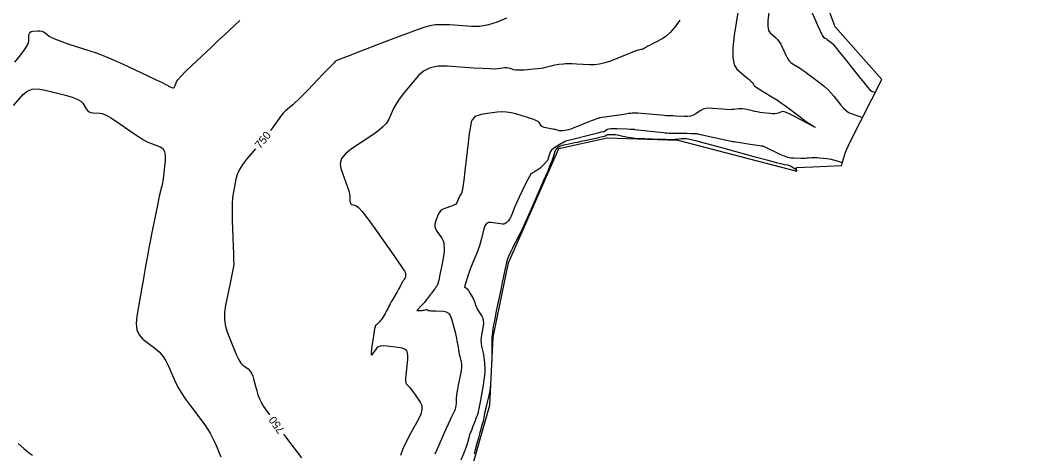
# Model space of a CAD drawing. Extents: x 2079879 to 2092887, y 778083 to 784051.
# Drawn here: x 2084488.3 to 2084844.9, y 780660.6 to 780812.3 of the extents above; entities that cross this region are included whole.
import ezdxf

# ---------------------------------------------------------------- set-up
doc = ezdxf.new("R2010")
doc.units = 0
for name, color, linetype in [('DT_X_Contour_Major', 7, 'Continuous'), ('DT_X_Contour_Minor', 7, 'Continuous'), ('DT_X_TIN_Hull', 7, 'Continuous')]:
    doc.layers.add(name, color=color, linetype=linetype)

msp = doc.modelspace()

# ---------------------------------------------------------------- linework, layer by layer
at = {"layer": 'DT_X_Contour_Major'}
for points in [[(2084658.31, 780813.13), (2084655.13, 780811.71), (2084652.04, 780810.75), (2084649.04, 780810.25), (2084646.14, 780810.21), (2084638.53, 780810.73), (2084635.85, 780810.83), (2084633.5, 780810.74), (2084631.49, 780810.47), (2084629.82, 780810.01), (2084625.82, 780808.53), (2084624.06, 780807.88), (2084621.76, 780807.01), (2084618.92, 780805.94), (2084615.56, 780804.65), (2084605.87, 780800.96), (2084602.68, 780799.73), (2084600.39, 780798.84), (2084598.99, 780798.27), (2084598.48, 780798.04), (2084598.32, 780797.84), (2084598.02, 780797.52), (2084597.24, 780796.7), (2084595.97, 780795.38), (2084594.23, 780793.56), (2084588.94, 780788.05), (2084587.11, 780786.17), (2084585.61, 780784.67), (2084584.43, 780783.54), (2084583.56, 780782.79), (2084581.7, 780781.29), (2084580.99, 780780.66), (2084580.26, 780779.9), (2084579.52, 780779.01), (2084578.76, 780777.99), (2084576.71, 780775.1), (2084575.84, 780773.91), (2084575.81, 780773.87)], [(2084486.28, 780797.73), (2084488.42, 780800.3), (2084489.95, 780802.35), (2084490.88, 780803.88), (2084491.2, 780804.9), (2084491.24, 780806.92), (2084491.34, 780807.58), (2084491.6, 780808.08), (2084492.04, 780808.39), (2084492.64, 780808.53), (2084494.47, 780808.66), (2084495.13, 780808.65), (2084495.76, 780808.53), (2084496.35, 780808.28), (2084496.91, 780807.92), (2084498.33, 780806.8), (2084499.14, 780806.32), (2084500.51, 780805.72), (2084502.44, 780805.01), (2084504.92, 780804.18), (2084512.27, 780801.82), (2084515.08, 780800.85), (2084518.02, 780799.72), (2084521.08, 780798.44), (2084524.26, 780796.99), (2084532.9, 780792.9), (2084535.76, 780791.55), (2084537.84, 780790.55), (2084539.16, 780789.91), (2084539.7, 780789.62), (2084540.12, 780789.34), (2084540.29, 780789.23), (2084540.48, 780789.13), (2084540.7, 780789.03), (2084540.93, 780788.94), (2084541.59, 780788.69), (2084541.83, 780788.67), (2084542.04, 780788.8), (2084542.24, 780789.07), (2084542.42, 780789.48), (2084542.86, 780790.77), (2084543.33, 780791.5), (2084544.39, 780792.71), (2084546.04, 780794.39), (2084548.29, 780796.56), (2084555.08, 780802.98), (2084557.5, 780805.26), (2084559.65, 780807.28), (2084561.54, 780809.05), (2084563.18, 780810.56), (2084565.06, 780812.3)], [(2084570.49, 780767.38), (2084567.54, 780763.88), (2084566.07, 780761.98), (2084564.93, 780760.14), (2084564.12, 780758.38), (2084563.64, 780756.69), (2084562.79, 780752.27), (2084562.53, 780750.4), (2084562.38, 780748.11), (2084562.33, 780745.4), (2084562.39, 780742.27), (2084562.71, 780733.36), (2084562.81, 780730.43), (2084562.88, 780728.34), (2084562.92, 780727.09), (2084562.94, 780726.67), (2084562.93, 780726.68), (2084562.92, 780726.65), (2084562.9, 780726.55), (2084562.87, 780726.39), (2084562.83, 780726.17), (2084562.72, 780725.5), (2084562.61, 780724.95), (2084562.38, 780723.8), (2084562.02, 780722.05), (2084561.53, 780719.69), (2084560.05, 780712.62), (2084559.67, 780710.02), (2084559.66, 780707.54), (2084559.99, 780705.17), (2084560.69, 780702.91), (2084563.03, 780697.04), (2084563.88, 780695.05), (2084564.68, 780693.49), (2084565.43, 780692.34), (2084566.13, 780691.62), (2084567.92, 780690.27), (2084568.56, 780689.64), (2084569.11, 780688.79), (2084569.59, 780687.7), (2084569.99, 780686.38), (2084570.95, 780682.55), (2084571.37, 780681.14), (2084571.91, 780679.77), (2084572.58, 780678.44), (2084573.37, 780677.16), (2084575.38, 780674.19)], [(2084580.31, 780667.4), (2084581.34, 780666.04), (2084586.65, 780659.08)]]:
    msp.add_lwpolyline(points, dxfattribs=at)
at = {"layer": 'DT_X_Contour_Minor'}
for points in [[(2084740.08, 780820.26), (2084738.06, 780807.18), (2084737.55, 780802.76), (2084737.52, 780799.3), (2084737.99, 780796.82), (2084738.94, 780795.3), (2084742.14, 780792.56), (2084743.2, 780791.64), (2084743.98, 780790.93), (2084744.48, 780790.43), (2084744.69, 780790.15), (2084744.89, 780789.69), (2084745.14, 780789.42), (2084745.72, 780788.98), (2084746.65, 780788.37), (2084747.91, 780787.58), (2084751.74, 780785.24), (2084753.17, 780784.34), (2084754.58, 780783.39), (2084755.98, 780782.41), (2084757.37, 780781.38), (2084761.06, 780778.58), (2084762.32, 780777.63), (2084763.37, 780776.86), (2084764.19, 780776.27), (2084764.79, 780775.87), (2084766.09, 780775.05), (2084766.3, 780774.9), (2084765.94, 780775.06), (2084765.03, 780775.53), (2084763.55, 780776.32), (2084758.87, 780778.83), (2084757.28, 780779.63), (2084756.02, 780780.15), (2084755.1, 780780.38), (2084754.51, 780780.34), (2084753.37, 780779.83), (2084752.88, 780779.68), (2084752.24, 780779.61), (2084751.46, 780779.61), (2084750.55, 780779.69), (2084747.91, 780780), (2084746.96, 780780.13), (2084746.06, 780780.27), (2084745.22, 780780.44), (2084744.44, 780780.62), (2084742.43, 780781.14), (2084741.69, 780781.3), (2084740.98, 780781.39), (2084740.3, 780781.41), (2084739.64, 780781.36), (2084737.92, 780781.13), (2084737.19, 780781.07), (2084736.29, 780781.06), (2084735.22, 780781.1), (2084733.99, 780781.2), (2084730.47, 780781.52), (2084729.23, 780781.56), (2084728.12, 780781.46), (2084727.16, 780781.2), (2084726.35, 780780.79), (2084724.36, 780779.49), (2084723.57, 780779.08), (2084722.68, 780778.8), (2084721.69, 780778.65), (2084720.61, 780778.64), (2084717.61, 780778.79), (2084716.6, 780778.85), (2084715.83, 780778.88), (2084715.31, 780778.91), (2084715.02, 780778.91), (2084714.57, 780778.92), (2084714.23, 780778.94), (2084713.53, 780779), (2084712.48, 780779.09), (2084711.07, 780779.22), (2084706.84, 780779.61), (2084705.42, 780779.74), (2084704.32, 780779.82), (2084703.54, 780779.87), (2084703.09, 780779.87), (2084702.32, 780779.83), (2084701.87, 780779.78), (2084701.08, 780779.68), (2084699.98, 780779.53), (2084698.54, 780779.31), (2084694.27, 780778.67), (2084692.87, 780778.45), (2084691.84, 780778.3), (2084691.21, 780778.2), (2084690.95, 780778.16), (2084690.79, 780778.12), (2084690.72, 780778.11), (2084690.62, 780778.08), (2084690.5, 780778.05), (2084690.34, 780778.02), (2084689.91, 780777.9), (2084689.59, 780777.79), (2084688.98, 780777.55), (2084688.06, 780777.18), (2084686.84, 780776.68), (2084683.19, 780775.17), (2084681.92, 780774.67), (2084680.88, 780774.29), (2084680.04, 780774.03), (2084679.42, 780773.9), (2084678.06, 780773.7), (2084677.58, 780773.65), (2084677.15, 780773.64), (2084676.79, 780773.67), (2084676.49, 780773.74), (2084675.77, 780773.98), (2084675.45, 780774.08), (2084675.03, 780774.18), (2084674.51, 780774.29), (2084673.9, 780774.41), (2084672.14, 780774.73), (2084671.53, 780774.87), (2084671.04, 780775.08), (2084670.65, 780775.33), (2084670.37, 780775.64), (2084669.78, 780776.54), (2084669.38, 780776.9), (2084668.62, 780777.3), (2084667.51, 780777.75), (2084666.03, 780778.23), (2084661.62, 780779.58), (2084659.97, 780780), (2084658.34, 780780.23), (2084656.73, 780780.28), (2084655.14, 780780.16), (2084650.91, 780779.57), (2084649.49, 780779.34), (2084648.38, 780779.07), (2084647.6, 780778.76), (2084647.15, 780778.43), (2084646.35, 780777.49), (2084646.04, 780776.72), (2084645.7, 780775.12), (2084645.32, 780772.69), (2084644.91, 780769.44), (2084643.77, 780759.65), (2084643.37, 780756.41), (2084643.05, 780754.03), (2084642.8, 780752.51), (2084642.61, 780751.85), (2084642.22, 780751.25), (2084642.07, 780750.99), (2084641.91, 780750.69), (2084641.75, 780750.32), (2084641.59, 780749.91), (2084641.14, 780748.73), (2084640.89, 780748.3), (2084640.46, 780747.91), (2084639.85, 780747.57), (2084639.06, 780747.26), (2084636.73, 780746.48), (2084635.93, 780746.12), (2084635.27, 780745.6), (2084634.74, 780744.94), (2084634.35, 780744.14), (2084633.51, 780741.79), (2084633.3, 780740.93), (2084633.3, 780740.1), (2084633.51, 780739.3), (2084633.94, 780738.53), (2084635.36, 780736.53), (2084635.83, 780735.8), (2084636.17, 780735.1), (2084636.39, 780734.44), (2084636.48, 780733.81), (2084636.55, 780732.18), (2084636.53, 780731.44), (2084636.42, 780730.45), (2084636.23, 780729.2), (2084635.94, 780727.7), (2084635.06, 780723.36), (2084634.76, 780721.92), (2084634.53, 780720.86), (2084634.38, 780720.19), (2084634.29, 780719.89), (2084634.14, 780719.61), (2084634.08, 780719.51), (2084634.04, 780719.44), (2084634, 780719.39), (2084633.97, 780719.36), (2084633.89, 780719.31), (2084633.86, 780719.28), (2084633.83, 780719.24), (2084633.8, 780719.19), (2084633.76, 780719.12), (2084633.67, 780718.93), (2084633.61, 780718.83), (2084633.5, 780718.67), (2084633.35, 780718.46), (2084633.16, 780718.19), (2084632.58, 780717.41), (2084632.37, 780717.12), (2084632.15, 780716.83), (2084631.95, 780716.56), (2084631.75, 780716.3), (2084631.21, 780715.61), (2084631.01, 780715.35), (2084630.81, 780715.09), (2084630.6, 780714.83), (2084630.39, 780714.56), (2084629.84, 780713.84), (2084629.61, 780713.55), (2084629.34, 780713.24), (2084629.03, 780712.91), (2084628.68, 780712.54), (2084626.95, 780710.77), (2084628.34, 780710.74), (2084628.63, 780710.74), (2084628.9, 780710.76), (2084629.16, 780710.79), (2084629.39, 780710.84), (2084630, 780710.99), (2084630.22, 780711.03), (2084630.42, 780711.04), (2084630.59, 780711.02), (2084630.74, 780710.97), (2084631.11, 780710.78), (2084631.36, 780710.71), (2084631.84, 780710.66), (2084632.56, 780710.61), (2084633.5, 780710.56), (2084636.32, 780710.46), (2084637.29, 780710.27), (2084638.08, 780709.77), (2084638.69, 780708.95), (2084639.12, 780707.82), (2084640.03, 780704.39), (2084640.35, 780703.16), (2084640.61, 780702.04), (2084640.83, 780701.02), (2084641, 780700.11), (2084641.39, 780697.84), (2084641.53, 780697), (2084641.69, 780696.19), (2084641.84, 780695.42), (2084642.01, 780694.67), (2084642.46, 780692.73), (2084642.57, 780691.91), (2084642.56, 780690.91), (2084642.45, 780689.74), (2084642.22, 780688.39), (2084641.45, 780684.55), (2084641.19, 780683.2), (2084641, 780682.01), (2084640.86, 780681.01), (2084640.79, 780680.17), (2084640.69, 780678.17), (2084640.62, 780677.45), (2084640.51, 780676.78), (2084640.34, 780676.17), (2084640.12, 780675.61), (2084639.47, 780674.2), (2084639.14, 780673.48), (2084638.65, 780672.4), (2084637.99, 780670.96), (2084637.17, 780669.14), (2084634.75, 780663.81), (2084633.94, 780661.97), (2084633.29, 780660.45)], [(2084750.1, 780814.94), (2084749.8, 780812.33), (2084749.79, 780810.3), (2084750.06, 780808.83), (2084750.62, 780807.94), (2084752.51, 780806.32), (2084753.19, 780805.66), (2084753.8, 780804.88), (2084754.35, 780803.99), (2084754.83, 780802.99), (2084756.04, 780800.17), (2084756.54, 780799.18), (2084757.13, 780798.33), (2084757.82, 780797.62), (2084758.6, 780797.04), (2084760.82, 780795.68), (2084761.71, 780795.12), (2084762.7, 780794.44), (2084763.81, 780793.64), (2084765.02, 780792.74), (2084768.41, 780790.16), (2084769.64, 780789.17), (2084770.79, 780788.12), (2084771.85, 780787.01), (2084772.82, 780785.85), (2084775.31, 780782.68), (2084776.24, 780781.6), (2084777.14, 780780.74), (2084778.03, 780780.11), (2084778.9, 780779.7), (2084782.91, 780778.32)], [(2084764.97, 780815.83), (2084767.18, 780810.66), (2084767.93, 780808.94), (2084768.54, 780807.68), (2084768.99, 780806.86), (2084769.29, 780806.5), (2084769.9, 780806.13), (2084770.14, 780805.98), (2084770.41, 780805.79), (2084770.72, 780805.57), (2084771.05, 780805.32), (2084771.97, 780804.62), (2084772.52, 780804.09), (2084773.45, 780803), (2084774.78, 780801.38), (2084776.5, 780799.21), (2084781.61, 780792.69), (2084783.32, 780790.54), (2084784.63, 780788.97), (2084785.53, 780787.99), (2084786.02, 780787.6), (2084787.38, 780787.13)], [(2084719, 780812.4), (2084717.2, 780810.02), (2084715.6, 780808.15), (2084714.21, 780806.81), (2084713.03, 780805.98), (2084710.15, 780804.49), (2084709.17, 780803.97), (2084708.39, 780803.56), (2084707.79, 780803.25), (2084707.4, 780803.03), (2084706.61, 780802.58), (2084706.31, 780802.43), (2084706, 780802.3), (2084705.68, 780802.19), (2084705.36, 780802.11), (2084704.48, 780801.92), (2084703.95, 780801.75), (2084703.01, 780801.41), (2084701.66, 780800.9), (2084699.91, 780800.2), (2084694.68, 780798.1), (2084692.75, 780797.43), (2084690.89, 780796.97), (2084689.09, 780796.74), (2084687.36, 780796.73), (2084682.83, 780796.99), (2084681.27, 780797.07), (2084679.98, 780797.1), (2084678.97, 780797.1), (2084678.24, 780797.05), (2084676.65, 780796.86), (2084676.03, 780796.78), (2084675.38, 780796.66), (2084674.69, 780796.52), (2084673.96, 780796.34), (2084671.96, 780795.82), (2084671.14, 780795.64), (2084670.2, 780795.48), (2084669.12, 780795.35), (2084667.92, 780795.23), (2084664.53, 780794.96), (2084663.35, 780794.89), (2084662.36, 780794.89), (2084661.56, 780794.95), (2084660.95, 780795.07), (2084659.58, 780795.5), (2084659.04, 780795.62), (2084658.44, 780795.68), (2084657.8, 780795.68), (2084657.11, 780795.61), (2084655.2, 780795.35), (2084654.14, 780795.29), (2084652.39, 780795.32), (2084649.96, 780795.43), (2084646.84, 780795.63), (2084637.61, 780796.27), (2084634.39, 780796.25), (2084631.63, 780795.69), (2084629.34, 780794.6), (2084627.51, 780792.98), (2084623.28, 780787.94), (2084621.81, 780786.12), (2084620.58, 780784.43), (2084619.6, 780782.86), (2084618.86, 780781.43), (2084617.22, 780777.79), (2084616.36, 780776.39), (2084615.02, 780774.91), (2084613.2, 780773.37), (2084610.9, 780771.75), (2084604.13, 780767.33), (2084601.99, 780765.65), (2084600.65, 780763.94), (2084600.12, 780762.2), (2084600.39, 780760.41), (2084602.17, 780755.61), (2084602.76, 780753.95), (2084603.18, 780752.6), (2084603.44, 780751.54), (2084603.53, 780750.78), (2084603.55, 780749.16), (2084603.61, 780748.61), (2084603.8, 780748.18), (2084604.11, 780747.87), (2084604.55, 780747.68), (2084605.87, 780747.33), (2084606.6, 780746.79), (2084607.82, 780745.43), (2084609.51, 780743.26), (2084611.69, 780740.26), (2084618.13, 780731.18), (2084620.25, 780728.16), (2084621.77, 780725.92), (2084622.68, 780724.45), (2084623, 780723.75), (2084623.03, 780722.92), (2084623.03, 780722.62), (2084622.99, 780722.38), (2084622.93, 780722.18), (2084622.83, 780722.02), (2084622.51, 780721.66), (2084622.39, 780721.5), (2084622.26, 780721.29), (2084622.11, 780721.04), (2084621.96, 780720.75), (2084621.53, 780719.91), (2084621.32, 780719.51), (2084621.01, 780718.94), (2084620.59, 780718.21), (2084620.08, 780717.32), (2084618.56, 780714.72), (2084618.05, 780713.82), (2084617.64, 780713.09), (2084617.34, 780712.53), (2084617.15, 780712.13), (2084616.78, 780711.3), (2084616.62, 780710.96), (2084616.42, 780710.58), (2084616.17, 780710.14), (2084615.89, 780709.66), (2084615.07, 780708.32), (2084614.77, 780707.85), (2084614.48, 780707.43), (2084614.19, 780707.08), (2084613.91, 780706.78), (2084613.18, 780706.08), (2084612.93, 780705.84), (2084612.74, 780705.66), (2084612.61, 780705.52), (2084612.53, 780705.44), (2084612.42, 780705.3), (2084612.35, 780705.04), (2084612.22, 780704.39), (2084612.05, 780703.33), (2084611.82, 780701.86), (2084611.15, 780697.43), (2084610.99, 780696.06), (2084611, 780695.28), (2084611.2, 780695.09), (2084611.57, 780695.5), (2084612.81, 780697.36), (2084613.39, 780697.95), (2084614.22, 780698.32), (2084615.3, 780698.46), (2084616.62, 780698.39), (2084620.47, 780697.89), (2084621.74, 780697.66), (2084622.67, 780697.34), (2084623.26, 780696.93), (2084623.5, 780696.43), (2084623.69, 780694.97), (2084623.73, 780694.33), (2084623.71, 780693.52), (2084623.64, 780692.53), (2084623.51, 780691.35), (2084623.08, 780688), (2084622.97, 780686.86), (2084622.98, 780685.97), (2084623.11, 780685.34), (2084623.34, 780684.95), (2084624.12, 780684.25), (2084624.47, 780683.88), (2084624.93, 780683.3), (2084625.5, 780682.52), (2084626.19, 780681.53), (2084628.16, 780678.6), (2084628.68, 780677.41), (2084628.75, 780676.01), (2084628.38, 780674.42), (2084627.56, 780672.64), (2084624.78, 780667.61), (2084623.84, 780665.87), (2084623.09, 780664.44), (2084622.55, 780663.31), (2084622.21, 780662.48), (2084621.55, 780660.67), (2084621.3, 780659.92)], [(2084485.84, 780782.47), (2084489.2, 780786.36), (2084490.63, 780787.56), (2084492.41, 780788.22), (2084494.52, 780788.34), (2084496.98, 780787.94), (2084504, 780786.15), (2084506.35, 780785.47), (2084508.15, 780784.78), (2084509.4, 780784.07), (2084510.1, 780783.35), (2084511.23, 780781.41), (2084511.7, 780780.77), (2084512.28, 780780.31), (2084512.95, 780780.02), (2084513.73, 780779.92), (2084515.93, 780779.89), (2084516.92, 780779.69), (2084518.24, 780779.13), (2084519.89, 780778.2), (2084521.88, 780776.91), (2084527.62, 780772.97), (2084529.64, 780771.62), (2084531.4, 780770.54), (2084532.91, 780769.73), (2084534.16, 780769.19), (2084537.14, 780768.08), (2084538.09, 780767.47), (2084538.7, 780766.46), (2084538.97, 780765.04), (2084538.91, 780763.23), (2084538.29, 780757.86), (2084538.09, 780756.1), (2084537.92, 780754.85), (2084537.81, 780754.12), (2084537.74, 780753.9), (2084537.62, 780753.99), (2084537.51, 780753.65), (2084537.26, 780752.57), (2084536.87, 780750.74), (2084536.34, 780748.17), (2084534.74, 780740.32), (2084534.18, 780737.51), (2084533.67, 780734.95), (2084533.23, 780732.65), (2084532.86, 780730.61), (2084531.94, 780725.51), (2084531.57, 780723.49), (2084531.18, 780721.25), (2084530.75, 780718.8), (2084530.29, 780716.13), (2084529.01, 780708.72), (2084528.79, 780706.14), (2084529.07, 780703.95), (2084529.86, 780702.15), (2084531.16, 780700.74), (2084535.31, 780697.51), (2084536.78, 780696.21), (2084538.06, 780694.73), (2084539.17, 780693.07), (2084540.09, 780691.24), (2084542.32, 780686.11), (2084543.28, 780684.12), (2084544.51, 780681.99), (2084546.01, 780679.72), (2084547.77, 780677.31), (2084552.83, 780670.71), (2084554.71, 780667.81), (2084556.57, 780664.07), (2084558.41, 780659.5)], [(2084775.87, 780762.4), (2084773.33, 780763.25), (2084772.74, 780763.42), (2084772.05, 780763.57), (2084771.27, 780763.7), (2084770.39, 780763.81), (2084767.91, 780764.07), (2084767.04, 780764.15), (2084766.3, 780764.19), (2084765.68, 780764.21), (2084765.18, 780764.18), (2084764.03, 780764.07), (2084763.53, 780764.04), (2084762.91, 780764.02), (2084762.16, 780764.01), (2084761.29, 780764.01), (2084758.79, 780764.04), (2084757.81, 780764.12), (2084756.75, 780764.36), (2084755.6, 780764.74), (2084754.37, 780765.28), (2084748.43, 780768.12), (2084748.32, 780768.2), (2084748.21, 780768.22), (2084747.93, 780768.27), (2084747.48, 780768.34), (2084746.87, 780768.43), (2084743.62, 780768.91), (2084739.35, 780769.54), (2084738.55, 780769.66), (2084737.97, 780769.75), (2084737.61, 780769.8), (2084737.48, 780769.82), (2084737.43, 780769.82), (2084737.19, 780769.87), (2084736.5, 780770.02), (2084735.36, 780770.28), (2084733.78, 780770.63), (2084728.96, 780771.7), (2084727.36, 780772.05), (2084726.19, 780772.31), (2084725.43, 780772.47), (2084725.1, 780772.53), (2084724.77, 780772.58), (2084724.47, 780772.6), (2084723.82, 780772.62), (2084722.82, 780772.64), (2084721.47, 780772.67), (2084717.4, 780772.73), (2084716.06, 780772.76), (2084715.09, 780772.77), (2084714.49, 780772.79), (2084714.26, 780772.79), (2084714.15, 780772.8), (2084713.91, 780772.83), (2084713.28, 780772.9), (2084712.26, 780773.02), (2084710.84, 780773.18), (2084703.31, 780774.05), (2084703.13, 780774.08), (2084702.94, 780774.1), (2084702.42, 780774.12), (2084701.59, 780774.16), (2084700.44, 780774.22), (2084696.95, 780774.37), (2084695.77, 780774.4), (2084694.84, 780774.37), (2084694.16, 780774.28), (2084693.74, 780774.14), (2084692.35, 780773.33), (2084691.4, 780773.13), (2084691.03, 780773.05), (2084690.35, 780772.88), (2084689.34, 780772.62), (2084688, 780772.28), (2084681.04, 780770.47), (2084679.48, 780770.16), (2084679.1, 780770.04), (2084678.61, 780769.83), (2084678.01, 780769.51), (2084677.31, 780769.1), (2084675.31, 780767.87), (2084674.63, 780767.4), (2084674.1, 780766.91), (2084673.71, 780766.4), (2084673.47, 780765.86), (2084672.7, 780763.32), (2084671.02, 780761.51), (2084670.68, 780761.15), (2084670.37, 780760.85), (2084670.1, 780760.6), (2084669.86, 780760.42), (2084669.27, 780760), (2084669.03, 780759.84), (2084668.77, 780759.68), (2084668.49, 780759.5), (2084668.17, 780759.32), (2084667.3, 780758.82), (2084666.91, 780758.45), (2084666.4, 780757.69), (2084665.77, 780756.56), (2084665.01, 780755.04), (2084662.83, 780750.48), (2084662.08, 780748.92), (2084661.49, 780747.63), (2084661.05, 780746.61), (2084660.76, 780745.88), (2084660.18, 780744.3), (2084659.97, 780743.75), (2084659.77, 780743.3), (2084659.59, 780742.95), (2084659.43, 780742.7), (2084659.02, 780742.14), (2084658.85, 780741.95), (2084658.68, 780741.77), (2084658.49, 780741.61), (2084658.29, 780741.47), (2084657.74, 780741.12), (2084657.44, 780741.02), (2084656.96, 780741), (2084656.28, 780741.04), (2084655.42, 780741.16), (2084652.88, 780741.57), (2084652.01, 780741.54), (2084651.3, 780741.16), (2084650.77, 780740.41), (2084650.4, 780739.31), (2084649.63, 780735.9), (2084649.31, 780734.63), (2084648.93, 780733.36), (2084648.49, 780732.11), (2084647.98, 780730.86), (2084646.56, 780727.54), (2084646.05, 780726.34), (2084645.61, 780725.23), (2084645.24, 780724.19), (2084644.93, 780723.24), (2084643.65, 780719), (2084644.43, 780718.45), (2084644.62, 780718.27), (2084644.85, 780717.97), (2084645.13, 780717.56), (2084645.46, 780717.03), (2084646.39, 780715.47), (2084646.71, 780714.91), (2084646.97, 780714.4), (2084647.16, 780713.94), (2084647.29, 780713.54), (2084647.56, 780712.52), (2084647.7, 780712.11), (2084647.92, 780711.63), (2084648.22, 780711.08), (2084648.6, 780710.47), (2084649.71, 780708.74), (2084650.05, 780708.03), (2084650.23, 780707.2), (2084650.26, 780706.26), (2084650.14, 780705.2), (2084649.6, 780702.22), (2084649.44, 780701.13), (2084649.39, 780700.11), (2084649.45, 780699.14), (2084649.6, 780698.23), (2084650.14, 780695.9), (2084650.33, 780695.03), (2084650.47, 780694.16), (2084650.57, 780693.3), (2084650.64, 780692.45), (2084650.75, 780690.19), (2084650.74, 780689.2), (2084650.64, 780687.93), (2084650.44, 780686.39), (2084650.14, 780684.56), (2084649.22, 780679.32), (2084648.91, 780677.57), (2084648.67, 780676.25), (2084648.49, 780675.36), (2084648.38, 780674.91), (2084648.19, 780674.27), (2084648.09, 780673.95), (2084647.91, 780673.48), (2084647.67, 780672.86), (2084647.37, 780672.1), (2084646.47, 780669.84), (2084646.17, 780669.09), (2084645.94, 780668.52), (2084645.78, 780668.14), (2084645.7, 780667.94), (2084645.57, 780667.66), (2084645.51, 780667.49), (2084645.42, 780667.18), (2084645.3, 780666.74), (2084645.15, 780666.16), (2084644.71, 780664.43), (2084644.51, 780663.74), (2084644.24, 780662.94), (2084643.9, 780662.06), (2084643.5, 780661.07), (2084642.33, 780658.32)], [(2084759.92, 780759.91), (2084758.12, 780761.01), (2084757.73, 780761.23), (2084757.36, 780761.39), (2084756.98, 780761.52), (2084756.61, 780761.59), (2084755.64, 780761.74), (2084754.75, 780761.94), (2084752.82, 780762.44), (2084749.85, 780763.24), (2084745.84, 780764.34), (2084733.74, 780767.67), (2084729.7, 780768.78), (2084726.65, 780769.6), (2084724.58, 780770.15), (2084723.5, 780770.41), (2084721.93, 780770.73), (2084721.33, 780770.83), (2084720.72, 780770.88), (2084720.1, 780770.88), (2084719.47, 780770.83), (2084717.76, 780770.64), (2084717.2, 780770.58), (2084716.79, 780770.53), (2084716.53, 780770.51), (2084716.43, 780770.5), (2084716.36, 780770.5), (2084716.08, 780770.51), (2084715.3, 780770.53), (2084714.01, 780770.58), (2084712.22, 780770.64), (2084706.77, 780770.81), (2084704.87, 780770.9), (2084703.27, 780771.01), (2084701.96, 780771.15), (2084700.94, 780771.32), (2084698.61, 780771.83), (2084697.79, 780771.99), (2084697.08, 780772.12), (2084696.46, 780772.2), (2084695.95, 780772.24), (2084694.73, 780772.3), (2084694.3, 780772.3), (2084693.94, 780772.27), (2084693.65, 780772.21), (2084693.43, 780772.12), (2084692.93, 780771.83), (2084692.58, 780771.69), (2084691.92, 780771.51), (2084690.93, 780771.27), (2084689.63, 780770.99), (2084685.74, 780770.16), (2084684.37, 780769.87), (2084683.16, 780769.62), (2084682.12, 780769.4), (2084681.24, 780769.22), (2084679.12, 780768.79), (2084678.38, 780768.63), (2084677.78, 780768.46), (2084677.3, 780768.29), (2084676.94, 780768.12), (2084676.16, 780767.64), (2084675.89, 780767.41), (2084675.63, 780767.06), (2084675.41, 780766.61), (2084675.2, 780766.04), (2084674.7, 780764.38), (2084674.34, 780763.41), (2084673.66, 780761.73), (2084672.66, 780759.34), (2084671.32, 780756.24), (2084667.33, 780747.05), (2084665.94, 780743.89), (2084664.78, 780741.3), (2084663.84, 780739.27), (2084663.13, 780737.8), (2084661.52, 780734.66), (2084660.96, 780733.56), (2084660.48, 780732.61), (2084660.1, 780731.82), (2084659.79, 780731.18), (2084659.1, 780729.69), (2084658.84, 780729.07), (2084658.6, 780728.34), (2084658.37, 780727.49), (2084658.15, 780726.53), (2084657.58, 780723.8), (2084657.33, 780722.61), (2084657, 780721.07), (2084656.61, 780719.2), (2084656.14, 780716.97), (2084654.79, 780710.59), (2084654.34, 780708.4), (2084653.99, 780706.6), (2084653.74, 780705.21), (2084653.6, 780704.22), (2084653.35, 780702.1), (2084653.27, 780701.32), (2084653.22, 780700.56), (2084653.2, 780699.81), (2084653.2, 780699.08), (2084653.26, 780697.17), (2084653.26, 780696.3), (2084653.24, 780695.14), (2084653.19, 780693.69), (2084653.11, 780691.93), (2084652.86, 780686.87), (2084652.75, 780685.07), (2084652.59, 780683.49), (2084652.39, 780682.12), (2084652.15, 780680.96), (2084651.45, 780678.14), (2084651.21, 780677.14), (2084651.01, 780676.26), (2084650.84, 780675.49), (2084650.71, 780674.83), (2084650.43, 780673.24), (2084650.31, 780672.61), (2084650.15, 780671.94), (2084649.97, 780671.22), (2084649.75, 780670.44), (2084649.12, 780668.31), (2084648.88, 780667.49), (2084648.64, 780666.6), (2084648.38, 780665.66), (2084648.12, 780664.66), (2084647.41, 780661.91), (2084647.03, 780660.51)], [(2084487.48, 780664.14), (2084489.47, 780662.37), (2084491.16, 780661.01), (2084492.55, 780660.07)]]:
    msp.add_lwpolyline(points, dxfattribs=at)
at = {"layer": 'DT_X_TIN_Hull'}
msp.add_lwpolyline([(2084637.81, 780626.01), (2084652.52, 780677.63), (2084653.65, 780701.38), (2084659.1, 780727.43), (2084676.71, 780767.49), (2084693.52, 780771.17), (2084718.35, 780770.37), (2084759.96, 780759.54), (2084759.83, 780760.8), (2084765.52, 780760.99), (2084775.61, 780761.48), (2084776.97, 780766.2), (2084778.47, 780769.58), (2084789.66, 780791.63), (2084773.31, 780810.06), (2084767.42, 780826.11), (2084767.43, 780838.4), (2084771.77, 780859.71), (2084789.95, 780881.58), (2084810.58, 780902.42), (2084824.32, 780923.19), (2084853.89, 780949.55)], dxfattribs=at)

# ---------------------------------------------------------------- texts
at = {"layer": 'DT_X_Contour_Major'}
for rotation, p in [(50.7001, (2084572.2, 780767.16)), (126.0021, (2084580.86, 780668.93))]:
    msp.add_text('750', height=2.8, rotation=rotation, dxfattribs=at).set_placement(p)

doc.saveas('drawing.dxf')
